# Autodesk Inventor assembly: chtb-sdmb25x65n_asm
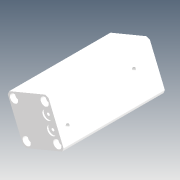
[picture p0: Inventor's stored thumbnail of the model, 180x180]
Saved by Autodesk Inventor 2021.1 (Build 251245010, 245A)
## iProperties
Company: Microsoft
Created: 2018-05
Part Number: chtb-sdmb25x65n_asm
Description: STEP AP214
Document SubType Name: Assembly
Designer: user
Title: chtb-sdmb25x65n_asm.STEP
Author: Windows
Revision Number: ÈÎºÎ
Sending System: SolidWorks 2015
Preprocessor: SwSTEP 2.0
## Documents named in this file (4)
- D:\Vault_2016\Projekty\Clamptek\Hydraulic\CHTB\CHTB-25\Inventor\chtb-sdmb25x65n\chtb-sdmb25x65n_asm.iam
- D:\Vault_2016\Projekty\Clamptek\Hydraulic\CHTB\CHTB-25\Inventor\chtb-sdmb25x65n\CHTB-25QG.ipt
- D:\Vault_2016\Projekty\Clamptek\Hydraulic\CHTB\CHTB-25\Inventor\chtb-sdmb25x65n\CHTB-SDMB25X65NBT.ipt
- D:\Vault_2016\Projekty\Clamptek\Hydraulic\CHTB\CHTB-25\Inventor\chtb-sdmb25x65n\CHTB-SDMB25X65NHSG.ipt
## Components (3 placed, 3 different names)
1. CHTB-25QG_1
2. CHTB-SDMB25X65NBT_2
3. CHTB-SDMB25X65NHSG_3
